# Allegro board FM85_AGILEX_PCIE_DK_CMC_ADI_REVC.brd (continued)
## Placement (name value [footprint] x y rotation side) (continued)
C1119  47uF  [0603]  144.66 71.47 180 bottom
C1120  47uF  [0603]  149.36 42.62 0 top
C1121  10uF  [0402]  127.09 57.31 240 bottom
C1122  10uF  [0402]  127.89 58.69 240 bottom
C1123  DNI  [0402]  127.81 55 240 bottom
C1124  47uF  [0603]  144.53 67.6 180 bottom
C1125  47uF  [0603]  144.66 63.6 180 bottom
C1126  DNI  [0603]  149.52 63.73 0 bottom
C1127  10uF  [0402]  144.79 58.11 90 bottom
C1128  10uF  [0402]  131.08 55.93 240 bottom
C1129  10uF  [0402]  130.28 57.31 60 bottom
C1130  10uF  [0402]  131.05 54.11 240 bottom
C1131  10uF  [0402]  128.73 55.93 120 bottom
C1132  47uF  [0603]  101.75 55.58 120 bottom
C1133  47uF  [0805]  150.88 55.45 270 bottom
C1134  47uF  [0805]  150.88 52.91 270 bottom
C1135  1uF  [0201]  118.41 47.25 30 bottom
C1136  1uF  [0201]  116.81 47.25 30 bottom
C1137  1uF  [0201]  115.22 47.25 30 bottom
C1138  1uF  [0201]  130.67 82.7 270 bottom
C1139  1uF  [0201]  119.01 71.55 210 bottom
C1140  1uF  [0201]  117.42 71.52 210 bottom
C1141  1uF  [0201]  115.83 71.52 210 bottom
C1142  1uF  [0201]  114.23 71.52 210 bottom
C1143  1uF  [0201]  113.63 47.25 30 bottom
C1144  1uF  [0201]  125.39 56.8 210 bottom
C1145  1uF  [0201]  124.71 52.54 30 bottom
C1146  1uF  [0201]  125.39 66 210 bottom
C1147  1uF  [0201]  108.38 65.02 90 bottom
C1148  1uF  [0201]  108.35 60.2 270 bottom
C1149  1uF  [0201]  107.48 51.58 90 bottom
C1150  1uF  [0201]  107.86 54.04 210 bottom
C1151  1uF  [0201]  107.25 55.53 30 bottom
C1152  22uF  [0603]  82.56 60.63 90 top
C1153  22uF  [0603]  86.11 55.32 0 bottom
C1154  22uF  [0603]  87.56 52.02 180 bottom
C1155  22uF  [0603]  80.91 66.88 90 top
C1159  1uF  [0201]  109.64 70.14 330 bottom
C1160  1uF  [0201]  109.64 71.06 330 bottom
C1161  10uF  [0402]  83.45 44.39 270 top
C1162  1uF  [0201]  124.95 47.94 90 bottom
C1163  1uF  [0201]  124.57 49.43 150 bottom
C1164  10uF  [0402]  109.95 85.64 180 top
C1165  1uF  [0201]  111.29 50.35 30 bottom
C1166  1uF  [0201]  112.83 68.87 30 bottom
C1167  10uF  [0402]  192.66 76.61 180 bottom
C1168  1uF  [0201]  125.64 54.71 150 bottom
C1169  1uF  [0201]  125.44 60.64 210 bottom
C1170  1uF  [0201]  125.55 62.03 150 bottom
C1171  1uF  [0201]  108.05 63.35 30 bottom
C1172  1uF  [0201]  108.66 61.86 210 bottom
C1173  1uF  [0201]  125.58 58.62 210 bottom
C1174  1uF  [0201]  107.25 57.37 30 bottom
C1175  1uF  [0201]  125.59 63.93 150 bottom
C1176  22uF  [0603]  94.9 37.17 270 bottom
C1177  22uF  [0603]  96.67 37.17 270 bottom
C1178  22uF  [0603]  109.19 36.44 0 bottom
C1179  22uF  [0603]  105.99 36.44 180 bottom
C1180  47uF  [0603]  83.39 54.84 180 top
C1181  47uF  [0603]  83.34 45.84 180 top
C1182  47uF  [0603]  83.39 64.54 180 top
C1183  47uF  [0603]  83.39 62.94 180 top
C1184  47uF  [0603]  83.34 43.05 180 top
C1185  47uF  [0603]  83.34 47.44 180 top
C1186  4.7uF  [0402]  111.16 70.19 60 bottom
C1187  4.7uF  [0402]  112.75 69.75 120 bottom
C1188  4.7uF  [0402]  112.75 70.67 120 bottom
C1189  1uF  [0201]  111.54 71.35 270 bottom
C1190  10uF  [0402]  114.72 85.64 180 top
C1191  4.7uF  [0402]  114.34 69.75 120 bottom
C1192  4.7uF  [0402]  116.71 69.67 240 bottom
C1193  4.7uF  [0402]  115.94 70.67 120 bottom
C1194  1uF  [0201]  114.43 70.71 30 bottom
C1195  10uF  [0402]  117.91 85.64 180 top
C1196  4.7uF  [0402]  118.33 70.23 300 bottom
C1197  4.7uF  [0402]  119.92 69.73 240 bottom
C1198  4.7uF  [0402]  119.92 70.65 240 bottom
C1199  1uF  [0201]  117.61 70.71 30 bottom
C1200  10uF  [0402]  121.11 85.64 180 top
C1201  4.7uF  [0402]  123.11 69.88 240 bottom
C1202  4.7uF  [0402]  123.21 70.75 240 bottom
C1203  4.7uF  [0402]  121.49 69.75 240 bottom
C1204  1uF  [0201]  121.5 70.61 150 bottom
C1205  10uF  [0402]  108.61 85.6 180 top
C1208  4.7uF  [0402]  109.56 47.66 120 bottom
C1209  4.7uF  [0402]  111.15 49.03 60 bottom
C1210  4.7uF  [0402]  111.15 48.11 60 bottom
C1211  1uF  [0201]  109.64 48.63 30 bottom
C1212  10uF  [0402]  114.25 33.14 0 top
C1213  4.7uF  [0402]  115.11 48.11 300 bottom
C1214  4.7uF  [0402]  114.32 49.11 60 bottom
C1215  4.7uF  [0402]  113.52 48.11 300 bottom
C1216  1uF  [0201]  112.83 48.63 30 bottom
C1217  10uF  [0402]  112.34 33.14 0 top
C1218  4.7uF  [0402]  116.71 48.11 300 bottom
C1219  4.7uF  [0402]  118.3 49.03 300 bottom
C1220  4.7uF  [0402]  118.3 48.11 300 bottom
C1221  1uF  [0201]  116.62 48.98 210 bottom
C1222  10uF  [0402]  120.57 33.14 0 top
C1223  4.7uF  [0402]  121.46 49 300 bottom
C1224  4.7uF  [0402]  121.1 47.37 180 bottom
C1225  4.7uF  [0402]  119.89 48.11 300 bottom
C1226  1uF  [0201]  119.81 48.98 210 bottom
C1227  10uF  [0402]  119.51 33.14 0 top
C1232  1uF  [0201]  113.93 68.13 270 bottom
C1233  1uF  [0201]  115.52 68.13 270 bottom
C1234  1uF  [0201]  117.12 68.13 270 bottom
C1235  1uF  [0201]  118.69 68.23 270 bottom
C1236  1uF  [0201]  115.52 50.65 90 bottom
C1237  1uF  [0201]  118.31 51.34 330 bottom
C1238  1uF  [0201]  117.17 50.52 90 bottom
C1239  10uF  [0402]  82.39 52.14 270 top
C1240  10uF  [0402]  82.39 70.14 270 top
C1241  10uF  [0402]  84.39 52.14 90 top
C1242  10uF  [0402]  84.39 70.14 270 top
C1243  10uF  [0402]  82.39 53.14 270 top
C1244  1uF  [0201]  123.8 48.17 150 bottom
C1245  1uF  [0201]  123.02 48.98 210 bottom
C1246  10uF  [0402]  103.96 55.47 120 bottom
C1247  10uF  [0402]  128.67 52.77 270 bottom
C1248  10uF  [0402]  128.74 54.05 300 bottom
C1249  10uF  [0402]  100.75 64.65 120 bottom
C1250  10uF  [0402]  100.77 62.83 120 bottom
C1251  10uF  [0402]  100.77 60.99 120 bottom
C1255  1uF  [0201]  113.07 85.65 270.3 top
C1256  1uF  [0201]  112.38 85.65 270 top
C1257  1uF  [0201]  107.06 70.71 150 bottom
C1258  1uF  [0201]  107.06 69.79 150 bottom
C1259  1uF  [0201]  107.06 68.87 150 bottom
C1260  1uF  [0201]  123.8 47.25 150 bottom
C1261  1uF  [0201]  122.39 48.06 330 bottom
C1262  1uF  [0201]  106.46 68.3 330 bottom
C1265  22uF  [0603]  149.36 48.34 180 top
C1266  DNI  [0805]  150.88 50.5 270 bottom
C1267  1uF  [0201]  106.38 50.85 150 bottom
C1268  1uF  [0201]  104.86 54.15 30 bottom
C1269  1uF  [0201]  108.66 69.22 210 bottom
C1270  1uF  [0201]  108.66 68.3 210 bottom
C1271  4.7uF  [0402]  105.55 56.39 300 bottom
C1272  1uF  [0201]  102.88 65.48 90 bottom
C1273  1uF  [0201]  101.47 65.67 330 bottom
C1277  DNI  [1206]  148.34 69.67 0 bottom
C1279  1uF  [0201]  130.25 53.64 150 bottom
C1280  1uF  [0201]  103.56 56.69 270 bottom
C1283  1uF  [0201]  108.05 71.06 330 bottom
C1284  4.7uF  [0402]  80.94 72.79 270 top
C1286  1000pF  [0402]  244.1 48.34 90 bottom
C1293  1uF  [0402]  57.41 37.04 0 bottom
C1294  1uF  [0402]  58.43 42.24 180 bottom
C1309  10uF  [C0805]  67.83 43 90 bottom
C1310  0.1uF  [0402]  68.71 44.66 270 bottom
C1311  10uF  [C0805]  71.89 43 270 bottom
C1312  0.1uF  [0402]  71 44.66 90 bottom
C1313  4.7uF  [0402]  73.54 47.58 270 bottom
C1314  10uF  [0402]  104.88 51.24 120 bottom
C1315  10uF  [0402]  125.47 55.93 120 bottom
C1316  DNI  [0402]  106.37 53.18 120 bottom
C1317  47uF  [0603]  144.94 59.6 180 bottom
C1318  47uF  [0603]  149.52 59.09 0 bottom
C1319  DNI  [0603]  147.74 67.6 0 bottom
C1320  47uF  [0603]  149.52 57.4 0 bottom
C1321  10uF  [0402]  101.56 52.79 75 bottom
C1322  10uF  [0402]  103.66 52.96 180 bottom
C1323  10uF  [0402]  103.98 54.56 300 bottom
C1324  10uF  [0402]  102.88 52.48 180 bottom
C1325  47uF  [0603]  83.34 49.14 180 top
C1326  47uF  [0603]  99.27 52.66 180 bottom
C1327  0.1uF  [0402]  53.47 105.87 180 top
C1328  22pF  [0603]  55.51 106 0 top
C1329  2.2nF  [0402]  58.81 105.87 0 top
C1330  47pF  [0402]  58.81 104.09 0 top
C1331  0.1uF  [0402]  48.9 103.58 270 top
C1332  10uF  [0402]  57.28 102.69 90 top
C1333  10uF  [0805]  58.94 99.77 180 top
C1334  4.7uF  [0603]  49.16 99.77 90 top
C1335  10uF  [0805]  47.25 99.77 180 top
C1336  4.7uF  [0603]  57.03 99.77 90 top
C1338  330uf  [1210]  58.3 95.33 270 top
C1339  330uf  [1210]  47.89 95.2 270 top
C1340  100uF  [0805]  57.54 94.69 0 bottom
C1341  100uF  [0805]  47.38 94.76 0 bottom
C1342  47uF  [0603]  54.36 94.69 90 bottom
C1343  47uF  [0603]  50.3 94.76 90 bottom
C1345  0.1uF  [0402]  205.85 51.95 270 bottom
C1346  2.2uF  [0402]  201 52.66 270 bottom
C1347  DNI  [0402]  203.33 49.25 270 bottom
C1348  DNI  [0402]  201.43 48.39 270 bottom
C1350  2.2uF  [0402]  198.43 53.6 180 top
C1351  100uF  [1206]  197.15 54.93 270 bottom
C1354  100uF  [1206]  193.48 55.05 0 bottom
C1355  DNI  [1206]  192.92 55.25 0 top
C1356  100pf  [0402]  200.96 50.14 270 bottom
C1360  22uF  [1206]  208.41 52.38 90 top
C1361  22uF  [1206]  208.41 49.86 270 bottom
C1364  1uF  [0402]  206.05 54 0 top
C1366  0.1uF  [0402]  207.14 43.41 180 bottom
C1367  2.2uF  [0402]  202.48 43.84 180 bottom
C1368  DNI  [0402]  205.24 40.67 270 bottom
C1369  DNI  [0402]  201.43 40.72 90 bottom
C1371  2.2uF  [0402]  199.4 45.67 180 top
C1372  100uF  [1206]  198.05 40.72 90 bottom
C1375  100uF  [1206]  198.05 45.54 270 bottom
C1376  DNI  [1206]  200.34 45.29 270 bottom
C1381  22uF  [1206]  209.32 42.09 270 bottom
C1382  22uF  [1206]  209.32 42.09 270 top
C1385  1uF  [0402]  208.26 45.47 0 top
C1386  100uF  [1206]  197.01 54.82 270 top
C1387  100uF  [1206]  197.62 46.43 270 top
C1388  100pf  [0402]  203.29 42.17 0 bottom
C1389  1uF  [0402]  59.95 37.04 0 bottom
C1390  1uF  [0402]  60.84 40.97 90 bottom
C1391  1uF  [0402]  60.84 39.45 90 bottom
C1392  1uF  [0402]  56.14 37.04 0 bottom
C1393  0.1uF  [0402]  57.92 32.97 180 top
C1394  0.1uF  [0402]  61.73 32.97 180 top
C1395  1uF  [0402]  204.86 62.18 90 bottom
C1396  1uF  [0402]  204.86 64.77 90 bottom
C1397  1uF  [0402]  214.46 59.69 270 bottom
C1398  1uF  [0402]  210.93 59.39 90 bottom
C1399  0.1uF  [0402]  216.92 57.1 90 bottom
C1400  0.1uF  [0402]  209.02 58.63 90 top
C1401  22uF  [0402]  109.53 55.91 300.6 bottom
C1402  22uF  [0402]  108.74 56.39 300 bottom
C1403  22uF  [0402]  123.1 62.95 120 bottom
C1404  22uF  [0402]  109.54 58.7 300 bottom
C1405  22uF  [0402]  107.97 58.71 120 bottom
C1406  22uF  [0402]  109.54 61.45 300 bottom
C1407  22uF  [0402]  109.15 64.43 0 bottom
C1408  22uF  [0402]  124.67 61.12 300 bottom
C1409  22uF  [0402]  123.15 53.49 300 bottom
C1410  22uF  [0402]  123.07 57.36 120 bottom
C1411  22uF  [0402]  118.36 49.98 300 bottom
C1412  22uF  [0402]  116.77 51.61 300 bottom
C1413  22uF  [0402]  110.24 52.85 300 bottom
C1414  22uF  [0402]  108.7 51.99 120 bottom
C1415  22uF  [0402]  113.62 51.65 120 bottom
C1416  22uF  [0402]  118.68 53.38 0 bottom
C1417  22uF  [0402]  120.25 53.38 180 bottom
C1418  22uF  [0402]  124.78 54.25 240 bottom
C1419  22uF  [0402]  124.7 57.81 240 bottom
C1420  22uF  [0402]  123.91 65.25 120 bottom
C1421  22uF  [0402]  124.79 63.36 240 bottom
C1422  22uF  [0402]  123.8 62.44 120 bottom
C1423  22uF  [0402]  123.85 67.07 300 bottom
C1424  22uF  [0402]  122.38 65.87 120 bottom
C1425  22uF  [0402]  121.45 68.85 240 bottom
C1426  22uF  [0402]  117.24 66.35 180 bottom
C1427  22uF  [0402]  113.57 65.59 124.4 bottom
C1428  22uF  [0402]  115.96 67.01 115.7 bottom
C1429  22uF  [0402]  112.73 66.04 121.8 bottom
C1430  22uF  [0402]  110.37 66.5 302.6 bottom
C1431  47uF  [0603]  115.32 63.83 270 bottom
C1432  330uF  [3528_2MM]  159.37 52.53 0 bottom
C1433  330uF  [3528_2MM]  159.37 79.23 0 bottom
C1435  330uF  [3528_2MM]  159.37 48.06 0 bottom
C1436  330uF  [3528_2MM]  159.37 75.72 0 bottom
C1437  330uF  [3528_2MM]  159.52 35.11 0 bottom
C1438  220uF  [1206]  130.72 87.68 90 bottom
C1439  47uF  [0603]  115.93 54.92 90 bottom
C1440  330uF  [3528_2MM]  105.42 86.08 180 bottom
C1441  330uF  [3528_2MM]  123.15 33.35 0 bottom
C1442  330uF  [3528_2MM]  96.15 85.93 180 bottom
C1443  220uF  [1206]  109.76 33.12 180 bottom
C1444  220uF  [1206]  116.85 33.58 180 bottom
C1445  47uF  [0603]  149.16 66.04 180 bottom
C1446  47uF  [0603]  125.14 85.4 0 bottom
C1447  1uF  [0201]  114.33 54.08 210 bottom
C1448  1uF  [0201]  119.51 53.77 270 bottom
C1449  1uF  [0201]  117.81 64.8 90 bottom
C1450  100u  [CAPC2012X110L50L]  144.05 89.13 270 bottom
C1451  0.1uF  [0402]  47.76 25.96 270 top
C1452  0.1uF  [0402]  47.76 26.98 270 top
C1456  2.2uF  [0402]  185.43 38.79 315 bottom
C1533  2.2uF  [0402]  183.09 59.34 270 bottom
C1557  470uF  [CAPMP7343X300L130X240N_P079IN]  160.97 85.78 0 bottom
C1558  100uF  [CAPC2012X110L50L]  159.39 89.16 90 bottom
C1559  100uF  [CAPC2012X110L50L]  159.42 82.04 90 bottom
C1560  22uF  [CAPC3216X135L50N]  170.93 77.08 0 bottom
C1561  22uF  [CAPC3216X135L50N]  171.03 88.22 0 bottom
C1562  22uF  [CAPC3216X135L50N]  170.51 83.8 0 bottom
C1563  22uF  [CAPC3216X135L50N]  170.51 81.44 0 bottom
C1564  1uF  [CAPC1005X60L20L]  170.19 78.97 90 bottom
C1565  1uF  [CAPC1005X60L20L]  171.13 89 270 top
C1575  470uF  [CAPMP7343X300L130X240N_P079IN]  161.08 69.68 0 bottom
C1576  100uF  [CAPC2012X110L50L]  159.41 66.28 90 bottom
C1577  100uF  [CAPC2012X110L50L]  159.43 73.15 90 bottom
C1578  22uF  [CAPC3216X135L50N]  170.34 66.94 0 bottom
C1579  22uF  [CAPC3216X135L50N]  170.94 63.47 0 bottom
C1580  22uF  [CAPC3216X135L50N]  170.39 71.51 0 bottom
C1581  22uF  [CAPC3216X135L50N]  170.4 74.02 0 bottom
C1582  1uF  [CAPC1005X60L20L]  170.75 65.11 90 bottom
C1622  470uF  [CAPMP7343X300L130X240N_P079IN]  160.93 77.11 0 top
C1623  470uF  [CAPMP7343X300L130X240N_P079IN]  161.63 63.2 0 top
C1624  470uF  [CAPMP7343X300L130X240N_P079IN]  161.96 90.53 0 top
C1625  330 uF  [CT7343-43]  170.4 77.17 180 top
C1626  330 uF  [CT7343-43]  170.52 63.15 180 top
C1627  330 uF  [CT7343-43]  170.5 48.74 180 top
C1628  330 uF  [CT7361-20]  187.64 54.66 270 bottom
C1629  330 uF  [CT7343-43]  169.7 33.3 180 top
C1630  22uF  [CAPC3216X135L50N]  185.81 61.6 270 top
C1631  22uF  [CAPC3216X135L50N]  185.43 61.6 270 bottom
C1632  22uF  [CAPC3216X135L50N]  187.61 61.62 270 bottom
C1633  22uF  [CAPC3216X135L50N]  187.99 61.62 270 top
C1714  4.7uF  [0402]  186.11 58.47 90 top
C1715  2.2uF  [0603]  186.14 54.92 0 top
C1716  2.2uF  [0603]  186.14 57.33 0 top
C1718  1uF  [0402]  181.34 63.81 0 bottom
C1719  330pF  [0603]  178.65 62.16 90 bottom
C1720  100pF  [0402]  176.26 60.62 270 top
C1721  2200pF  [0402]  176.62 59.82 270 top
C1728  10uF  [0402]  173.51 69.01 0 bottom
C1729  1uF  [0402]  173.55 70.72 180 bottom
C1730  1uF  [0402]  170.82 61.81 90 bottom
C1731  1uF  [0402]  170.6 50.15 90 bottom
C1732  22uF  [CAPC3216X135L50N]  170.42 51.87 0 bottom
C1733  22uF  [CAPC3216X135L50N]  170.47 48.46 0 bottom
C1734  22uF  [CAPC3216X135L50N]  170.47 56.75 0 bottom
C1735  22uF  [CAPC3216X135L50N]  170.48 59.19 0 bottom
C1738  470uF  [CAPMP7343X300L130X240N_P079IN]  161.01 58.86 0 bottom
C1739  100uF  [CAPC2012X110L50L]  159.43 55.41 90 bottom
C1740  100uF  [CAPC2012X110L50L]  159.43 62.24 90 bottom
C1741  1uF  [0402]  170.6 46.73 90 bottom
C1742  1uF  [0402]  171.41 36.22 270 top
C1743  22uF  [CAPC3216X135L50N]  170.45 36.89 0 bottom
C1744  22uF  [CAPC3216X135L50N]  170.45 39.25 0 bottom
C1745  22uF  [CAPC3216X135L50N]  170.37 41.87 0 bottom
C1746  22uF  [CAPC3216X135L50N]  170.38 44.31 0 bottom
C1749  470uF  [CAPMP7343X300L130X240N_P079IN]  160.93 42.02 0 bottom
C1750  100uF  [CAPC2012X110L50L]  159.44 38.53 90 bottom
C1751  100uF  [CAPC2012X110L50L]  159.44 31.98 90 bottom
C1886  470uF  [D2E]  58.3 69.93 180 bottom
C1887  100uF  [1206]  73.35 63.74 90 bottom
C1888  100uF  [1206]  68.21 63.83 90 bottom
C1889  100uF  [1206]  75.77 63.74 90 bottom
C1890  220 uF  [CT7361-20]  64.6 81.4 90 bottom
C1891  22uF  [1206]  78.31 74.56 90 bottom
C1892  22uF  [1206]  75.8 74.56 90 bottom
C1893  22uF  [1206]  63.25 74.47 90 bottom
C1894  22uF  [1206]  65.71 74.47 90 bottom
C1958  22uF  [1206]  182.4 18.87 90 bottom
C1959  22uF  [1206]  193.07 18.93 90 bottom
C1960  1uF  [0402]  185.77 20.7 90 bottom
C1961  2.2uF  [0603]  180.32 15.83 270 bottom
C1962  100uF  [1206]  184.67 15.5 0 bottom
C1963  100uF  [1206]  190.89 15.5 180 bottom
C1964  100uF  [1206]  193.81 14.68 180 top
C1966  0.1uF,DNI  [0402]  184.27 24.61 180 bottom
C1967  0.1uF  [0402]  181.13 23 0 bottom
C2004  1.5nF  [0402]  191.24 78.06 180 bottom
C2028  47pF  [0402]  174.51 52.78 0 top
C7192  100nF  [C0402]  10.78 20.25 90 top
C7394  4u7  [C0402]  12.86 15.29 90 top
C7395  100nF  [C0402]  12.86 16.13 90 top
C7396  100nF  [C0402]  15.35 19.76 0 top
C7397  0.1uF  [0402]  4.91 23.35 315 bottom
C7398  0.1uF  [0402]  7.03 22.92 315 bottom
C7399  0.1uF  [0402]  135.59 36.02 270 top
C7400  0.1uF  [0402]  129.71 35.94 90 top
C7401  0.1uF  [0402]  47.2 20.78 0 top
C7402  0.1uF  [0402]  40.48 19.87 0 top
C7403  0.1uF  [0402]  201.07 20.48 180 top
C7404  0.1uF  [0402]  228.2 105.97 0 bottom
C7405  10uF  [0603]  26.42 31.91 90 bottom
C7406  1uF  [0402]  26.47 28.43 180 bottom
C7422  2.2uF  [0402]  186.47 94.39 180 bottom
C7423  22uF  [0603]  191.77 91.32 270 top
C7424  22uF  [0603]  193.21 91.32 270 top
C7425  22uF  [0603]  194.64 91.32 270 top
C7426  22uF  [0603]  196.08 91.32 270 top
C7427  22uF  [0603]  197.51 91.32 270 top
C7428  22uF  [0603]  199.74 92.34 0 top
C7429  22uF  [0603]  192.74 94.69 90 bottom
C7430  22uF  [0603]  191.37 95 90 bottom
C7431  22uF  [0603]  188.9 91.32 270 top
C7432  22uF  [0603]  190.34 91.32 270 top
C7433  0.1uF  [0402]  187.14 88.5 270 bottom
C7434  0.01uF  [0402]  189.29 94.52 90 bottom
C7435  0.1uF  [0402]  118.97 85.66 180 top
C7436  0.1uF  [0402]  119.98 85.66 180 top
C7437  0.1uF  [0402]  122.22 71.62 315 bottom
C7438  0.1uF  [0402]  120.69 71.65 302.9 bottom
C7439  0.01uF  [0402]  204.49 18.92 90 bottom
C7442  47uF  [C1206]  66.68 40.87 0 bottom
C7461  1500pF  [0402]  181.95 42.8 180 bottom
C7462  150pF  [0402]  183.03 41.72 180 bottom
C7463  0.1uF,DNI  [0402]  179.41 47.37 270 bottom
C7464  0.1uF,DNI  [0402]  195.08 44.64 0 top
C7465  150uF  [7343P_H2MM]  190.3 51.77 180 top
C7466  22uF  [1206]  189.57 37.39 90 bottom
C7467  22uF  [1206]  191.78 44.07 270 bottom
C7468  22uF  [1206]  189.69 44.02 270 bottom
C7469  22uF  [1206]  187.38 37.26 90 bottom
C7470  22uF  [1206]  186.39 40.69 0 bottom
C7471  10uF  [1206]  191.83 37.42 90 bottom
C7472  100uF  [1206]  181.87 30.53 90 bottom
C7473  100uF  [1206]  184.47 51.82 270 top
C7474  100uF  [1206]  182.19 51.82 270 top
C7475  100uF,DNI  [1206]  179.55 30.53 90 bottom
C7477  470uF  [2917]  180.36 29.09 180 top
C7478  470uF  [2917]  190.16 29.09 0 top
C7479  100uF  [1206]  186.44 30.53 90 bottom
C7480  100uF  [1206]  179.9 51.82 270 top
C7481  100uF  [1206]  184.15 30.53 90 bottom
C7517  22uF  [1206]  73.59 91.47 180 bottom
C7518  0.01uF  [0402]  68.04 86.55 270 bottom
C7519  47uF  [C1206]  74.23 82.81 180 bottom
C7520  47uF  [C1206]  78.72 90.6 180 top
C7521  22uF  [1206]  25.86 53.32 90 bottom
C7522  0.01uF  [0402]  16.87 58.77 270 bottom
C7523  47uF  [C1206]  27.16 61.26 270 bottom
C7524  47uF  [C1206]  25.47 66.83 270 bottom
C7525  1uF  [0402]  196.27 81.41 180 bottom
C7526  1uF  [0402]  71.53 89.31 90 bottom
C7556  1uF  [CAPC1005X60L20L]  170.1 75.53 90 bottom
C7557  470uF  [CAPMP7343X300L130X240N_P079IN]  161.37 48.69 0 top
C7558  4.7uF  [0402]  187.15 66.3 180 top
C7559  4.7uF  [0402]  187.15 69.45 0 top
C7560  10nF  [0402]  191.88 68.28 90 bottom
C7561  4.7uF  [0402]  193.88 67.19 0 top
C7562  4.7uF  [0402]  193.89 69.93 0 top
C7563  10nF  [0402]  200.59 67.87 0 top
C7564  22uF  [1206]  184.27 69.29 180 bottom
C7565  22uF  [1206]  180.47 68.1 90 bottom
C7566  100pf  [0402]  178.25 68.96 270 top
C7567  22nF  [0402]  184.92 67.36 0 top
C7568  1nF  [0402]  182.3 66 90 top
C7569  3.3nF  [0402]  184.92 66.45 0 bottom
C7571  47uF  [C1206]  74.99 32.82 180 bottom
C7572  22uF  [CAPC3216X135L50N]  191.41 63.74 0 bottom
C7574  1uF  [0402]  71.94 75.69 180 bottom
C7575  0.1uF  [0402]  41.85 20.08 180 top
C7578  1uF  [0402]  173.41 84.71 180 bottom
C7579  10uF  [0402]  173.51 82.78 0 bottom
C7580  1uF  [0402]  174.52 56.89 0 top
C7581  10uF  [0402]  174.52 55.02 180 top
C7582  1uF  [0402]  175.27 42.67 0 top
C7583  10uF  [0402]  174.95 40.59 180 top
C7584  470uF  [D2E]  58.28 65.13 180 bottom
C7585  100uF  [1206]  78.31 63.74 90 bottom
C7586  100uF  [1206]  65.58 63.74 90 bottom
C7587  100uF  [1206]  80.71 63.74 90 bottom
C7588  220 uF  [CT7361-20]  204.83 88.34 0 top
C7589  22uF  [1206]  198.61 78.18 90 top
C7590  22uF  [1206]  198.25 85.3 270 bottom
C7591  22uF  [1206]  198.61 83.9 270 top
C7592  22uF  [1206]  197.83 76.07 90 bottom
C7593  100uF  [1206]  176.97 77.08 0 top
C7594  100uF  [1206]  181.18 75.28 90 bottom
C7595  100uF  [1206]  181.19 75.33 90 top
C7596  470uF  [D2E]  177.58 75.46 270 bottom
C7597  100uF  [1206]  181.43 85.19 90 bottom
C7598  100uF  [1206]  181.32 85.16 90 top
C7599  100uF  [1206]  179.13 85.19 90 top
C7600  470uF  [D2E]  177.58 85.11 270 bottom
C7602  1uF  [0402]  196.45 66.8 180 bottom
C7603  22uF  [CAPC3216X135L50N]  192.34 60.25 0 top
C7604  1uF  [0402]  70.83 35.07 270 bottom
C7605  22uF  [1206]  72.8 40.76 180 bottom
C7606  22uF  [1206]  220.67 98.38 90 top
C7607  22uF  [1206]  205.26 98.38 90 top
C7608  1uF  [0402]  211.04 99.98 270 top
C7609  2.2uF  [0603]  206.5 105.2 90 top
C7610  100uF  [1206]  209.7 105.63 270 top
C7611  100uF  [1206]  217.32 105.71 270 top
C7612  100uF  [1206]  213.51 105.66 270 top
C7614  0.1uF,DNI  [0402]  212.32 97.35 180 top
C7615  0.1uF  [0402]  214.36 98.68 0 top
C7616  22uF  [1206]  77.2 54.77 90 bottom
C7617  22uF  [1206]  65.65 54.54 90 bottom
C7618  1uF  [0402]  69.48 55.04 180 bottom
C7619  2.2uF  [0603]  72.02 55.15 90 bottom
C7620  100uF  [1206]  72.22 49.94 0 top
C7621  100uF  [1206]  77.17 50.21 180 top
C7622  100uF  [1206]  67.24 49.94 180 top
C7624  0.1uF,DNI  [0402]  67.55 60.33 180 bottom
C7625  0.1uF  [0402]  64.38 58.67 0 bottom
C7626  22uF  [1206]  26.09 41.25 0 bottom
C7627  0.01uF  [0402]  32.87 36.92 0 bottom
C7630  22uF  [1206]  15.65 43.31 270 bottom
C7631  0.01uF  [0402]  21.55 36.53 0 bottom
C7632  47uF  [C1206]  21.12 41.05 0 bottom
C7634  47uF  [C1206]  32.96 43.41 0 bottom
C7636  22uF  [1206]  5.72 37.54 90 bottom
C7637  0.01uF  [0402]  9.71 37.19 0 bottom
C7638  47uF  [C1206]  9.87 43.16 0 bottom
C7639  47uF  [C1206]  9.87 40.88 0 bottom
C7640  22uF  [1206]  15.42 37.14 90 bottom
C7641  47uF  [C1206]  21.12 43.34 0 bottom
C7642  22pF  [0603]  24.01 37.54 0 bottom
C7643  22pF  [0603]  35.16 36.91 0 bottom
C7644  22pF  [0603]  16.39 62.41 90 bottom
C7645  22pF  [0603]  12.71 37.16 0 bottom
C7646  22uF  [1206]  26.07 43.56 0 bottom
C7647  47uF  [C1206]  32.96 41.15 0 bottom
C7648  22uF  [1206]  4 44.79 0 bottom
C7649  22uF  [1206]  28 53.32 90 bottom
C7650  1uF  [0402]  207.86 19.46 180 bottom
C7651  22pF  [0603]  68.56 83.47 270 bottom
C7652  22pF  [0603]  202.43 15.98 270 bottom
C7653  47uF  [C1206]  210.33 14.86 180 bottom
C7654  0.1uF  [0402]  192.06 61.6 270 bottom
C7655  1uF  [0402]  196.78 84.43 0 top
C7656  1uF  [0402]  68.13 75.7 90 bottom
C7660  1.5nF  [0402]  75.11 71.28 270 bottom
C7661  1000pF,DNI  [1206]  77.12 69.75 90 bottom
C7663  360pF,DNI  [0402]  188.22 78.21 270 bottom
C7664  0.1uF  [CAPC1005X60L20L]  178.7 58.12 0 bottom
C7665  0.01uF  [0402]  197.72 64.62 180 top
C7666  47uF  [C1206]  210.38 17 180 bottom
C7667  22uF  [1206]  209.18 25.78 270 bottom
C7668  22uF  [1206]  207.02 25.78 270 bottom
C7669  0.47uF  [0402]  176.21 63.27 90 bottom
C7670  0.47uF  [0402]  182.58 63.81 0 bottom
C7671  0.47uF  [0402]  175.62 62.77 180 top
C7672  0.47uF  [0402]  180.4 63.81 0 bottom
C7674  22uF  [1206]  68.76 91.49 0 bottom
C7676  12pF  [0402]  8.8 19.94 0 top
C7678  0.1uF  [CAPC1005X60L20L]  178.7 59.9 0 bottom
C7679  100uF  [CAPC2012X110L50L]  151.22 90.38 0 top
C7680  100uF  [CAPC2012X110L50L]  153.57 90.38 0 top
C7681  47pF  [0402]  173.54 74.12 0 bottom
C7682  47pF  [0402]  174.48 88.12 180 top
C7683  100pF,DNI  [0402]  198.99 64.62 180 top
C7684  22uF  [CAPC3216X135L50N]  191.42 60.11 0 bottom
C7685  22uF  [CAPC3216X135L50N]  198.53 68.35 270 bottom
C7686  47pF  [0402]  173.49 80.98 180 bottom
C7687  100uF  [CAPC2012X110L50L]  159.4 64.26 90 bottom
C7688  100uF  [CAPC2012X110L50L]  151.06 61.17 270 bottom
C7689  47pF  [0402]  174.5 66.37 180 top
C7690  47pF  [0402]  174.51 37.54 180 top
C7691  47pF  [0402]  175.52 44.86 90 top
C7692  47pF  [0402]  174.88 59.82 90 top
C7693  100uF  [CAPC2012X110L50L]  159.35 45.4 90 bottom
C7694  100uF  [CAPC2012X110L50L]  154.19 48.29 270 bottom
C7695  100uF  [CAPC2012X110L50L]  156.01 31.14 0 bottom
C7696  100uF  [CAPC2012X110L50L]  151.14 44.71 270 bottom
C7697  1uF  [0402]  18.35 44.2 180 bottom
C7698  100pF,DNI  [0402]  22.99 39.07 0 bottom
C7699  47uF  [C1206]  21.04 45.85 0 bottom
C7700  1uF  [0402]  30.21 44.3 180 bottom
C7701  47uF  [C1206]  37.8 44.63 180 bottom
C7702  100pF,DNI  [0402]  35.03 39.27 0 bottom
C7703  1uF  [0402]  7.12 43.23 180 bottom
C7704  1uF  [0402]  27.24 58.14 90 bottom
C7706  100pF,DNI  [0402]  11.69 38.81 0 bottom
C7707  100pF,DNI  [0402]  21.61 64.09 270 bottom
C7708  47uF  [C1206]  23.3 66.8 270 bottom
C7709  47uF  [C1206]  13.34 43.26 270 bottom
C7711  100pF,DNI  [0402]  71 83.52 270 bottom
C7712  47uF  [C1206]  78.72 88.42 180 top
C7713  22uF  [1206]  69.63 33.02 0 bottom
C7714  1uF  [0402]  73.95 88.14 270 bottom
C7715  100pf  [0402]  179.18 15.6 180 bottom
C7716  100pf  [0402]  206.62 95.29 180 top
C7717  100pf  [0402]  63.28 54.84 0 bottom
C7718  3.3nF, DNI  [0402]  183.65 66.75 270 bottom
C7719  22uF  [1206]  179.22 71.56 0 top
C7720  10pF  [0402]  65.03 60.53 0 bottom
C7721  10pF  [0402]  190.02 26.24 0 bottom
C7722  10pF  [0402]  211.52 96.32 0 top
C7723  100pf  [0402]  67.93 38.74 0 bottom
C7725  100pF,DNI  [0402]  205.06 16.26 270 bottom
C7726  2.2nF  [0402]  169.27 15.22 270 top
C7727  2.2nF  [0402]  171.48 27.64 0 top
C7728  2.2nF  [0402]  161.88 24.29 180 top
C7729  2.2nF  [0402]  162.03 17.27 0 top
C7730  2.2nF  [0402]  161.88 26.8 180 top
C7731  2.2nF  [0402]  161.96 21.31 180 top
C7732  2.2nF  [0402]  171.41 21.31 180 top
C7733  2.2nF  [0402]  171.41 23.6 0 top
C7734  2.2nF  [0402]  167.82 24.06 90 bottom
C7735  3.3nF  [0402]  169.5 26.44 90 bottom
C7736  3.3nF  [0402]  163.56 24.46 0 bottom
C7737  4.7nF  [0402]  170.42 28.93 270 bottom
C7738  4.7nF  [0402]  170.42 28.1 270 bottom
C7739  4.7nF  [0402]  163.02 28.93 90 bottom
C7740  0.47uF  [0402]  165.62 28.1 270 bottom
C7741  0.47uF  [0402]  169.96 21.39 0 bottom
C7742  0.47uF  [0402]  169.5 24.05 90 bottom
C7743  2.2nF  [0402]  67.37 24.36 180 top
C7744  2.2nF  [0402]  67.44 21.38 180 top
C7745  2.2nF  [0402]  67.52 17.35 0 top
C7746  2.2nF  [0402]  73.03 24.89 0 bottom
C7747  2.2nF  [0402]  76.89 17.2 180 top
C7748  2.2nF  [0402]  67.32 27.64 180 top
C7749  2.2nF  [0402]  76.97 27.71 0 top
C7750  2.2nF  [0402]  76.89 23.67 0 top
C7751  2.2nF  [0402]  76.89 21.38 180 top
C7752  3.3nF  [0402]  74.99 26.51 90 bottom
C7753  3.3nF  [0402]  69.04 24.53 0 bottom
C7754  4.7nF  [0402]  68.51 29 90 bottom
C7755  4.7nF  [0402]  75.9 29 270 bottom
C7756  4.7nF  [0402]  75.9 28.17 270 bottom
C7757  0.47uF  [0402]  68.18 23.22 0 bottom
C7758  0.47uF  [0402]  71.51 28.68 0 bottom
C7759  0.47uF  [0402]  74.99 24.12 90 bottom
C7760  4.7uF  [0402]  68.46 36.25 270 bottom
C7761  0.1uF  [0402]  233.13 38.61 0 top
C7764  47pF  [0402]  229.72 37.82 270 top
C7765  0.1uF  [0402]  236.15 42.37 90 bottom
C7766  10uF  [0805]  230.31 41.53 180 bottom
C7767  10uF  [0805]  238.94 44.61 0 top
C7768  4.7uF  [0603]  237.04 44.4 270 top
C7769  10uF  [0805]  228.1 44.2 0 top
C7770  4.7uF  [0603]  229.88 44.17 270 top
C7771  330uF  [7343P]  239.61 54.92 0 top
C7772  330uF  [7343P]  228.15 54.92 180 top
C7773  100uF  [0805]  228.3 51.44 270 top
C7774  100uF  [0805]  238.46 51.59 90 top
C7775  47uF  [0603]  238.16 49.76 0 top
C7776  47uF  [0603]  228.49 49.61 180 top
C7777  1uF  [0402]  205.26 22.94 90 bottom
C7778  1uF  [0402]  27.19 56.34 90 bottom
C7779  1uF  [0402]  5.42 40.8 0 bottom
C7780  100pf  [0402]  231.52 37.47 90 top
C7781  10pF  [0402]  232.06 38.64 0 top
C7783  220 uF  [CT7361-20]  240.7 38.61 270 bottom
CN1  0.1uF  [CAP_PACK_4_1206]  64.75 15.97 270 bottom
CN2  0.1uF  [CAP_PACK_4_1206]  69.68 13.31 0 bottom
CN3  0.1uF  [CAP_PACK_4_1206]  64.75 20.32 270 bottom
CN4  0.1uF  [CAP_PACK_4_1206]  175.14 15.98 270 top
CN5  0.1uF  [CAP_PACK_4_1206]  175.14 23.87 270 top
CN6  0.1uF  [CAP_PACK_4_1206]  175.14 19.89 270 top
D1  GREEN_LED  [LED_0603]  2.45 68.65 270 top
D2  APHB1608CGKSYKC  [LED0603_4PIN_APHB1608]  6.45 68.65 270 top
D3  GREEN_LED  [LED_0603]  10.45 68.65 270 top
D4  APHB1608CGKSYKC  [LED0603_4PIN_APHB1608]  14.45 68.65 270 top
D5  GREEN_LED  [LED_0603]  250.83 41.23 0 top
D6  BLUE LED  [LED_0603]  250.83 45.8 0 top
D7  GREEN_LED  [LED_0603]  250.83 39.7 0 top
D8  GREEN_LED  [LED_0603]  250.83 38.18 0 top
D9  RED_LED  [LED_0603]  250.83 44.27 0 top
D10  GREEN_LED  [LED_0603]  250.83 36.65 0 top
D11  GREEN_LED  [LED_0603]  250.83 42.75 0 top
D12  5p0SMDJ12A  [TVS_5P0SMDJ12A]  225.68 92.76 0 bottom
D13  5p0SMDJ12A  [TVS_5P0SMDJ12A]  205.54 70.28 0 bottom
D14  GREEN_LED  [LED_0603]  15.07 107.21 180 top
D17  PMEG2005AEL,315  [DIO_SOD882]  183.65 81.44 90 bottom
D18  PMEG2005AEL,315  [DIO_SOD882]  64.95 67.26 0 bottom
EU1  MAX31730ATC+  [LCC12_S30_50DF25X17MA]  73.12 80.24 270 top
EU2  MAX31730ATC+  [LCC12_S30_50DF25X17MA]  170.47 91.39 90 bottom
FB1  220ohm  [0402]  148.72 47.58 180 bottom
FB5  220ohm  [0402]  51.46 20.85 90 bottom
FB6  220ohm  [0402]  59.44 22.71 270 bottom
FB7  220ohm  [0402]  56.78 18.37 0 bottom
FB8  80ohm  [0805]  60.14 29.23 270 bottom
FB9  220ohm  [0402]  42.17 43.13 90 bottom
FB10  220ohm  [0402]  56.01 43.51 90 bottom
FB13  220ohm  [0402]  212.73 68.02 270 bottom
FB16  600 Ohm, 0.5A, 0.35DCR  [0603]  8.77 26.34 180 bottom
FB26  0.1uH, 19A  [SL1616A-R10MHF]  139.41 86.63 0 top
FB29  220ohm  [0402]  80.5 69.78 0 bottom
FB30  22ohm@100Mhz 8A  [0603]  84.46 59.26 180 bottom
FB31  22ohm@100Mhz 8A  [0603]  85.16 70.94 270 bottom
FB32  22ohm@100Mhz 8A  [0603]  84.97 45.29 180 bottom
FB33  22ohm@100Mhz 8A  [0603]  84.46 61.29 180 bottom
FB40  220ohm  [0402]  64.98 43 270 bottom
FB41  22ohm@100Mhz 8A  [0603]  84.46 57.36 180 bottom
HW1  -  [LIGHTPIPE_P-U90-1101-T00A-BP]  12.45 69.7 270 top
J1  DDR4x72x288  [DDR4DIMM_SMT]  132.47 96.34 180 top
J2  DDR4x72x288  [DDR4DIMM_SMT]  132.47 103.96 180 top
J3  -  [2027180100]  46.1 81.04 0 top
J4  -  [2027180100]  46.1 56.25 0 top
J5  PCIE_Slot  [PCIX-16PORT]  45.65 4.1 0 top
J6  MCIO_74P_G97V22312HR  [SCONN74_K64129002_PIP]  220.71 16.58 180 top
J7  MCIO_74P_G97V22312HR  [SCONN74_K64129002_PIP]  220.71 45.29 180 top
J8  MICRO_USB_CONN  [MOLEX-MICRO-USB-47589-001]  1.45 28.3 90 top
J9  FAN_Conn  [MOLEX_0470533000]  248.17 24.46 270 top
J10  70247-1051  [MOLEX_70247-1051]  224.16 99.4 0 top
J11  PCIe 2x4 ATX  [MLX_SD-5569_8POS_RA]  240.11 96.54 270 top
J12  TSW-103-08-G-S  [1X3_HDR_TH]  227.05 17.4 0 top
J13  TSW-103-08-G-S  [1X3_HDR_TH]  237.03 17.47 0 top
J14  TSW-103-08-G-S  [1X3_HDR_TH]  2.42 37.67 90 top
J15  TSW-103-08-G-S  [1X3_HDR_TH]  235.88 25.29 90 top
L1  1uH  [IFSC1008ABER1R0M01]  46.77 78.85 0 bottom
L2  1uH  [IFSC1008ABER1R0M01]  46.77 84.94 0 bottom
L3  1uH  [IFSC1008ABER1R0M01]  46.77 87.99 0 bottom
L4  1uH  [IFSC1008ABER1R0M01]  46.77 54.05 0 bottom
L5  1uH  [IFSC1008ABER1R0M01]  46.77 60.15 0 bottom
L6  1uH  [IFSC1008ABER1R0M01]  46.77 63.2 0 bottom
L11  BLM15AG221SN1  [0402]  21.37 35.08 270 bottom
L12  BLM15AG221SN1  [0402]  23.51 33.73 270 bottom
L13  BLM15AG221SN1  [0402]  20.97 32.17 180 bottom
L14  BLM15AG221SN1  [0402]  29.55 27.41 0 bottom
L20  0.82uH  [XEL4020-821]  39.02 95.15 270 top
L21  0.82uH  [XEL4020-821]  198.91 35.26 180 top
L22  0.20uH  [XEL4030-201ME]  53.09 95.2 270 top
L23  72 nH  [IND_FP0805-CUS]  162.23 56.06 180 top
L26  1uH  [IFSC1008ABER1R0M01]  180.6 68.4 90 top
L27  72 nH  [IND_FP0805-CUS]  162.23 83.87 180 top
L28  72 nH  [IND_FP0805-CUS]  162.23 70.16 180 top
L29  72 nH  [IND_FP0805-CUS]  162.23 41.35 180 top
L30  0.35 uH  [IND_XGL5030]  233.36 49.35 90 top
MTH1  MT_HOLE_GND  [MH_D125C175T_TB315]  249.01 16.65 0 top
MTH2  MT_HOLE_GND  [MH_D125C175T_TB315]  7.5 104.65 180 bottom
MTH4  MT_HOLE_GND  [MH_D125C175T_TB315]  249.03 106.14 0 top
MTH5  MT_HOLE_GND  [MH_D125C175T_TB315]  7.5 9.35 0 top
NOREF  -  []  74.4 33.94 90 top
NOREF#2  -  []  233.36 47.7 90 top
NOREF#3  -  []  178.59 64.54 0 top
NOREF#4  -  []  68.88 38.66 90 top
NOREF#5  -  []  45 0.5 0 top
NOREF#6  -  []  173.6 66.16 90 top
NOREF#7  -  []  197.99 58.31 90 top
NOREF#8  -  []  237.65 34.96 0 top
NOREF#9  -  []  205.36 96.07 0 top
NOREF#10  -  [unnamed#2]  5.67 96.01 0 top
NOREF#11  -  []  200.26 59.06 90 top
NOREF#12  -  [unnamed#3]  117.46 13.51 0 top
NOREF#13  -  []  159.67 56.06 0 top
NOREF#14  -  []  173.66 72.64 90 top
NOREF#15  -  []  254 12.75 0 top
NOREF#16  -  []  61.55 83.85 0 top
NOREF#17  -  []  33.35 4.5 0 top
NOREF#18  -  [unnamed#3]  100.19 10.36 0 top
NOREF#19  -  []  129.3 0.5 0 top
NOREF#20  -  []  41.35 10.92 0 top
NOREF#21  -  [unnamed#3]  173.28 27.01 0 top
NOREF#22  -  []  7.75 113.69 0 top
NOREF#23  -  []  181.13 17.48 0 top
NOREF#24  -  []  168.58 87.2 90 top
NOREF#25  -  []  68.15 33.94 0 top
NOREF#26  -  []  166.04 58.92 0 top
NOREF#27  -  [unnamed#3]  84.43 10.36 0 top
NOREF#28  -  []  41.35 10.92 0 top
NOREF#29  -  []  159.67 83.87 0 top
NOREF#30  -  []  7.5 94.75 0 top
NOREF#31  -  []  44.45 9.62 0 top
NOREF#32  -  []  168.6 74.16 0 top
NOREF#33  -  []  168.54 44.35 90 top
NOREF#34  -  []  7.5 104.88 0 top
NOREF#35  -  []  237.65 34.96 90 top
NOREF#36  -  []  166.04 72.64 0 top
NOREF#37  -  []  60.08 -68.63 0 top
NOREF#38  -  []  139.03 11 0 top
NOREF#39  -  []  166.04 30.12 0 top
NOREF#40  -  []  0 4.5 0 top
NOREF#41  -  []  36.14 14.57 0 top
NOREF#42  -  []  178.59 56.54 90 top
NOREF#43  -  []  147.3 10.21 0 top
NOREF#44  -  []  179.98 25.79 0 top
NOREF#45  -  []  58.1 0.5 0 top
NOREF#46  -  []  7.5 94.75 0 top
NOREF#47  -  []  7.5 9.35 0 top
NOREF#48  -  []  230.62 51.99 0 top
NOREF#49  -  [unnamed#3]  68.68 10.36 0 top
NOREF#50  -  []  0.01 123.85 0 top
NOREF#51  -  [unnamed#3]  244.47 21.49 0 top
NOREF#52  -  []  183.51 88.74 0 top
NOREF#53  -  []  38.32 14.29 90 top
NOREF#54  -  []  166.04 44.83 0 top
NOREF#55  -  []  173.66 30.12 90 top
NOREF#56  -  []  201.18 91.39 0 top
NOREF#57  -  []  74.4 33.94 90 top
NOREF#58  -  []  68.15 33.94 0 top
NOREF#59  -  []  68.85 77.75 90 top
NOREF#60  -  [unnamed#3]  242.37 101.24 0 top
NOREF#61  -  []  190.69 64.41 0 top
NOREF#62  -  []  0 111.15 0 top
NOREF#63  -  []  182.39 67.57 0 top
NOREF#64  -  []  35.82 16.29 0 top
NOREF#65  -  []  62.67 64.68 90 top
NOREF#66  -  []  58.29 0.31 0 top
NOREF#67  -  []  173.52 52.16 90 top
NOREF#68  -  []  -309.9 -46.1 0 top
NOREF#69  -  []  168.48 88.2 0 top
NOREF#70  -  []  179.98 16.79 90 top
NOREF#71  -  [unnamed#2]  91.2 10.37 0 top
NOREF#72  -  []  63.23 52.46 90 top
NOREF#73  -  []  159.67 70.16 0 top
NOREF#74  -  []  182.64 67.32 0 top
NOREF#75  -  []  168.62 59.16 90 top
NOREF#76  -  []  168.52 60.16 0 top
NOREF#77  -  []  168.44 45.35 0 top
NOREF#78  -  []  0 4.5 0 top
NOREF#79  -  []  7.5 94.75 0 top
NOREF#80  -  []  15 4.5 0 top
NOREF#81  -  []  56.2 0.5 0 top
NOREF#82  -  [unnamed#3]  150.5 36.53 0 top
NOREF#83  -  [unnamed#3]  65.33 27.26 0 top
NOREF#84  -  []  7.5 9.35 0 top
NOREF#85  -  []  36.14 14.57 90 top
NOREF#86  -  []  143.35 2.95 0 top
NOREF#87  -  []  64.38 53.15 0 top
NOREF#88  -  []  173.48 80.2 90 top
NOREF#89  -  []  62.67 64.68 0 top
NOREF#90  -  []  194.54 86.45 90 top
NOREF#91  -  []  45.5 0 0 top
NOREF#92  -  [unnamed#3]  81.92 82.25 0 top
NOREF#93  -  []  206.51 104.38 0 top
NOREF#94  -  [unnamed#3]  150.5 82.25 0 top
NOREF#95  -  []  132.04 3.45 0 top
NOREF#96  -  []  63.68 75.71 0 top
NOREF#97  -  []  15 12.75 0 top
NOREF#98  -  []  168.7 73.16 90 top
NOREF#99  -  []  63.23 61.46 0 top
NOREF#100  -  []  173.44 37.35 90 top
NOREF#101  -  []  183.51 63.34 90 top
NOREF#102  -  []  183.51 72.74 90 top
NOREF#103  -  []  7.5 9.35 0 top
NOREF#104  -  []  173.66 58.92 90 top
NOREF#105  -  [unnamed#3]  9.88 98.64 0 top
NOREF#106  -  []  7.5 104.88 0 top
NOREF#107  -  []  194.6 58.48 90 top
NOREF#108  -  []  144.74 5.32 0 top
NOREF#109  -  [unnamed#3]  81.92 36.53 0 top
NOREF#110  -  []  173.66 44.83 90 top
NOREF#111  -  []  159.67 41.35 0 top
NOREF#112  -  []  68.88 38.66 90 top
NOREF#113  -  []  205.36 96.07 90 top
NOREF#114  -  []  194.6 64.73 0 top
NOREF#115  -  []  56.2 7.45 0 top
NOREF#116  -  []  195.18 59.06 0 top
NOREF#117  -  []  230.62 46.71 90 top
NOREF#118  -  [unnamed#3]  242.37 101.24 180 bottom
NOREF#119  -  [unnamed#3]  244.47 21.49 180 bottom
NOREF#120  -  [unnamed#3]  9.88 98.64 180 bottom
Q1  FDV305N  [SOT23]  17.41 76.28 0 bottom
Q2  FDV305N  [SOT23]  21.09 76.28 0 bottom
Q3  FDV305N  [SOT23]  24.77 76.28 0 bottom
Q4  FDV305N  [SOT23]  29.47 71.83 0 bottom
Q5  FDV305N  [SOT23]  28.46 76.28 0 bottom
Q6  FDV305N  [SOT23]  32.27 76.28 0 bottom
Q7  FDV305N  [SOT23]  246.26 40.72 90 bottom
Q8  FDV305N  [SOT23]  246.26 44.78 90 bottom
Q9  FDV305N  [SOT23]  246.9 40.72 270 top
Q10  FDV305N  [SOT23]  246.26 36.65 90 bottom
Q11  FDV305N  [SOT23]  246.9 36.65 270 top
Q12  FDV305N  [SOT23]  246.9 44.78 270 top
Q13  PSMN1R0-30YLD  [NFET_PSMN1R0-30YLD]  218.96 80.85 180 top
Q14  SI2302CDS-T1-GE3  [SOT23]  213.49 89.49 270 bottom
Q15  FDV305N  [SOT23]  14.79 103.91 0 top
R1  240  [0402]  96.74 24.85 270 bottom
R2  240  [0402]  117.06 24.82 270 bottom
R3  240  [0402]  95.33 25.8 90 bottom
R4  240  [0402]  115.65 25.79 90 bottom
R7  240  [0402]  86.6 25.43 0 bottom
R8  240  [0402]  106.9 25.01 270 bottom
R9  240  [0402]  85.18 25.8 90 bottom
R10  240  [0402]  105.49 25.82 90 bottom
R13  1K  [0402]  70.2 28.98 270 bottom
R14  1K  [0402]  74.59 28.54 180 bottom
R15  1K  [0402]  70.99 27.33 90 bottom
R16  1K  [0402]  72.8 27.33 270 bottom
R17  1K  [0402]  67.74 27.46 270 bottom
R18  1K  [0402]  74.99 27.3 90 bottom
R19  1K  [0402]  70.2 26.51 270 bottom
R20  1K  [0402]  72.8 26.51 270 bottom
R21  1K  [0402]  70.2 25.69 90 bottom
R22  1K  [0402]  72.8 28.15 270 bottom
R23  1K  [0402]  72.8 28.98 270 bottom
R24  240  [0402]  75.89 24.93 270 bottom
R25  240  [0402]  74.99 25.72 90 bottom
R27  36  [0402]  70.67 15.95 0 bottom
R28  1K  [0402]  77.28 17.15 0 bottom
R29  DNI  [0402]  67.49 16.83 270 bottom
R30  1K  [0402]  67.49 17.66 270 bottom
R31  DNI  [0402]  76.98 19.3 90 bottom
R32  DNI  [0402]  66.91 23.43 270 bottom
R33  0  [0402]  76.98 20.17 270 bottom
R34  36  [0402]  66.91 22.61 90 bottom
R35  36  [0402]  72.22 22.85 180 bottom
R36  36  [0402]  73.11 22.85 180 bottom
R37  240  [0402]  117.91 82.89 0 bottom
R39  240  [0402]  130.31 24.77 270 bottom
R40  240  [0402]  140.47 24.77 270 bottom
R41  240  [0402]  128.87 25.71 90 bottom
R42  240  [0402]  139.03 25.71 90 bottom
R45  240  [0402]  150.63 24.77 270 bottom
R46  240  [0402]  160.34 24.85 270 bottom
R47  240  [0402]  149.19 25.71 90 bottom
R48  240  [0402]  159.35 25.71 90 bottom
R51  1K  [0402]  164.71 28.91 270 bottom
R52  1K  [0402]  169.11 28.46 180 bottom
R53  1K  [0402]  165.51 27.26 90 bottom
R54  1K  [0402]  167.31 27.26 270 bottom
R55  1K  [0402]  162.25 27.39 270 bottom
R56  1K  [0402]  169.51 27.23 90 bottom
R57  1K  [0402]  164.71 26.44 270 bottom
R58  1K  [0402]  167.31 26.44 270 bottom
R59  1K  [0402]  164.71 25.62 90 bottom
R60  1K  [0402]  167.31 28.08 270 bottom
R61  1K  [0402]  167.31 28.91 270 bottom
R62  240  [0402]  170.4 24.86 270 bottom
R63  240  [0402]  169.5 25.65 90 bottom
R65  36  [0402]  165.82 16.26 0 bottom
R66  1K  [0402]  172.1 17.46 90 bottom
R67  DNI  [0402]  162.91 17.54 90 bottom
R68  1K  [0402]  162.91 16.74 90 bottom
R69  DNI  [0402]  172.38 19.21 90 bottom
R70  DNI  [0402]  162.01 23.36 270 bottom
R71  0  [0402]  172.38 20.08 270 bottom
R72  36  [0402]  162.01 22.54 90 bottom
R73  36  [0402]  166.68 22.7 180 bottom
R74  36  [0402]  167.57 22.7 180 bottom
R75  240  [0402]  124.33 82.7 0 bottom
R77  0  [1206]  196.15 98.14 180 bottom
R78  0  [1206]  196.15 95.68 180 bottom
R79  0  [0402]  114.19 92.99 0 bottom
R80  10.0K  [0402]  92.82 95.79 270 bottom
R81  10.0K  [0402]  91.14 95.76 90 bottom
R82  10.0K, DNI  [0402]  118.39 92.94 180 bottom
R83  10.0K  [0402]  94.06 104.9 270 bottom
R84  0  [0402]  73.79 98.76 90 bottom
R85  0  [0402]  73.03 100.03 90 bottom
R86  0  [0402]  111.64 92.95 0 bottom
R87  10.0K  [0402]  146.49 98.71 180 bottom
R88  DNI  [0402]  147.34 99.82 180 bottom
R89  DNI  [0402]  145.65 99.82 180 bottom
R90  DNI  [0402]  146.36 92.87 0 bottom
R91  10.0K  [0402]  141.82 94.47 90 bottom
R94  0  [0603]  69.88 93.6 180 bottom
R95  0  [1206]  196.15 103.08 180 bottom
R96  0  [1206]  196.15 105.51 180 bottom
R97  0  [0402]  114.21 100.49 0 bottom
R98  10.0K, DNI  [0402]  100.57 104.88 90 bottom
R99  10.0K  [0402]  102.24 104.88 270 bottom
R100  10.0K  [0402]  70.84 105.44 0 bottom
R101  0  [0402]  72.52 107.39 180 bottom
R102  0  [0402]  111.65 102.59 180 bottom
R103  DNI  [0402]  145.57 107.37 180 bottom
R104  DNI  [0402]  146.57 102.72 180 bottom
R107  0  [0603]  68.18 101.32 0 bottom
R108  240  [0402]  126.45 34.8 270 top
R121  DNI  [0402]  43.19 88.72 90 bottom
R122  0  [0402]  43.19 87.71 90 bottom
R123  10.0K  [0402]  43.95 75.64 270 bottom
R124  10.0K  [0402]  45.85 75.64 270 bottom
R125  1M  [0402]  21.6 70.82 0 bottom
R126  DNI  [0402]  44.08 51.11 90 bottom
R127  0  [0402]  44.08 52.12 90 bottom
R128  10.0K  [0402]  45.93 52.12 270 bottom
R129  10.0K  [0402]  45.93 51.13 270 bottom
R130  1M  [0402]  35.21 67.11 180 bottom
R131  4.7K  [0402]  14.89 84.46 90 bottom
R132  4.7K  [0402]  43.95 76.66 90 bottom
R133  4.7K  [0402]  45.85 76.66 90 bottom
R134  4.7K  [0402]  24.88 79.45 180 bottom
R135  4.7K  [0402]  25.88 79.45 180 bottom
R136  10.0K  [0402]  14.89 82.21 270 bottom
R137  10.0K, DNI  [0402]  14.89 81.21 90 bottom
R138  DNI  [0402]  97.12 66.38 240 bottom
R139  1.50K  [0402]  97.14 56.39 240 bottom
R140  DNI  [0402]  99.59 69.98 0 bottom
R141  499E  [0402]  97.13 67.38 60 bottom
R142  DNI  [0402]  100 66.51 60 bottom
R143  DNI  [0402]  97.12 68.41 240 bottom
R144  DNI  [0402]  97.12 60.88 300 bottom
R145  DNI  [0402]  102.47 69.3 90 bottom
R146  1K  [0402]  104.17 69.95 0 bottom
R147  4.7K  [0402]  50.05 11.01 0 bottom
R148  4.7K  [0402]  50.93 11 180 top
R149  4.7K  [0402]  51.7 11 0 bottom
R150  10.0K  [0402]  53.73 11 0 top
R151  DNI  [0402]  54.24 10.62 90 bottom
R152  DNI  [0402]  54.74 11 180 top
R153  4.7K  [0402]  52.71 11 0 bottom
R154  10.0K  [0402]  55.63 11 0 bottom
R155  10.0K  [0402]  54.24 11.51 270 bottom
R156  4.7K  [0402]  58.17 11 180 bottom
R157  4.7K  [0402]  97.72 33.27 270 bottom
R158  100K  [0402]  73.77 11 0 top
R159  49.9  [0402]  59.21 11 180 top
R160  49.9  [0402]  65.92 11 0 bottom
R161  49.9  [0402]  75 12.35 270 top
R162  49.9  [0402]  78.75 11 0 bottom
R163  49.9  [0402]  80.53 11 0 bottom
R164  49.9  [0402]  125.04 12.35 90 top
R165  49.9  [0402]  96.53 11 0 bottom
R166  49.9  [0402]  60.33 11 180 top
R167  49.9  [0402]  80.53 11 180 top
R168  49.9  [0402]  96.78 11 180 top
R169  49.9  [0402]  120.8 11 180 top
R170  10.0K, DNI  [0402]  48.83 15.57 0 top
R171  10.0K, DNI  [0402]  49.18 19.33 180 top
R172  10.0K, DNI  [0402]  48.43 20.64 90 top
R173  10.0K, DNI  [0402]  58.68 16.33 180 bottom
R174  10.0K  [0402]  57.16 16.72 90 bottom
R175  10.0K  [0402]  48.34 19.33 0 top
R176  10.0K  [0402]  48.67 17.68 0 top
R177  10.0K  [0402]  48.02 15.57 180 top
R178  49.9  [0402]  99 53.85 90 bottom
R179  49.9  [0402]  99.02 51.24 60.6 bottom
R182  150  [0402]  99.85 55.14 120 bottom
R183  10.0K  [0402]  57.92 13.16 90 bottom
R184  0  [0402]  58.04 14.53 270 bottom
R185  0  [0402]  212.43 21.94 270 top
R186  0  [0402]  212.43 22.95 270 top
R187  0,DNI  [0402]  220.73 22.56 270 bottom
R188  0,DNI  [0402]  218.26 50.52 0 bottom
R189  0,DNI  [0402]  218.83 61.04 0 bottom
R190  49.9  [0402]  133.44 55.49 240 bottom
R191  49.9  [0402]  133.44 58.25 240 bottom
R194  150  [0402]  132.67 57.77 240 bottom
R195  10.0K  [0402]  138.36 35.28 0 bottom
R196  0  [0402]  138.36 33.43 0 bottom
R197  DNI  [0402]  132.67 63.29 240 bottom
R198  10.0K  [0402]  2.8 86.57 90 bottom
R199  10.0K  [0402]  2.8 81.36 90 bottom
R200  10.0K  [0402]  2.8 83.52 90 bottom
R201  10.0K  [0402]  2.8 85.55 90 bottom
R202  0  [0402]  2.8 84.53 270 bottom
R203  0  [0402]  2.8 80.34 270 bottom
R204  1K  [0402]  14.87 87.58 90 bottom
R205  0  [0402]  2.8 82.5 270 bottom
R206  1K  [0402]  14.87 88.6 90 bottom
R207  1K  [0402]  14.87 89.61 90 bottom
R208  1K  [0402]  14.87 90.63 90 bottom
R209  240  [0402]  101.48 83.14 90 bottom
R210  2K  [0402]  97.74 82.13 270 bottom
R211  10.0K  [0402]  1.47 14.32 270 top
R212  10.0K  [0402]  5.6 24.43 180 top
R213  1K  [0402]  99.58 82.14 90 bottom
R214  10.0K  [0402]  103.86 82.64 180 bottom
R215  10.0K  [0402]  104.86 82.64 180 bottom
R216  1K  [0402]  101.49 82.18 90 bottom
R217  10.0K  [0402]  105.85 82.64 180 bottom
R218  10.0K  [0402]  107.83 82.76 180 bottom
R219  10.0K  [0402]  106.85 82.64 180 bottom
R220  0  [0402]  128.43 82.67 0 bottom
R221  0  [0402]  127.43 82.67 0 bottom
R223  1K  [0402]  61.22 19.64 90 top
R224  4.7K  [0402]  54.67 29.57 90 bottom
R225  1K  [0402]  59.32 17.1 0 top
R226  10.0K  [0402]  51.32 16.84 0 top
R227  10.0K  [0402]  50.43 16.84 0 top
R228  4.7K  [0402]  54.31 21.01 270 bottom
R229  0  [0402]  61.22 28.03 270 top
R230  0  [0402]  61.22 27.02 270 top
R231  0  [0402]  61.25 26.09 270 top
R232  0  [0402]  61.25 25.07 270 top
R235  0  [0402]  47.76 24.08 90 top
R236  0  [0402]  47.76 25.1 90 top
R237  0  [0402]  49 22.38 180 top
R239  0  [0402]  49.13 27.66 180 bottom
R241  DNI  [0402]  50.43 33.86 0 top
R242  1K  [0402]  49.41 33.86 0 top
R243  DNI  [0402]  46.87 43.26 180 top
R244  1K  [0402]  47.89 43.26 180 top
R245  DNI  [0402]  52.46 33.86 0 top
R246  1K  [0402]  51.44 33.86 0 top
R247  DNI  [0402]  52.59 41.61 90 top
R248  1K  [0402]  52.59 40.59 90 top
R249  0  [0402]  47.38 33.86 180 top
R250  0  [0402]  48.39 33.86 180 top
R251  1K  [0402]  45.85 43.26 180 top
R252  0  [0402]  52.59 36.53 270 top
R253  1K  [0402]  44.84 43.26 180 top
R254  0  [0402]  52.59 37.54 270 top
R255  0  [0402]  52.59 38.56 270 top
R256  0  [0402]  52.59 39.58 270 top
R257  DNI  [0402]  45.35 33.86 0 top
R258  0  [0402]  44.33 33.86 180 top
R259  0  [0402]  49.92 43.26 0 top
R260  1K  [0402]  46.36 33.86 0 top
R261  0  [0402]  43.31 33.86 180 top
R262  0  [0402]  48.9 43.26 0 top
R263  1K  [0402]  42.93 35.64 270 top
R264  DNI  [0402]  42.93 36.65 270 top
R267  1K  [0402]  62.36 43.08 180 top
R268  DNI  [0402]  58.81 45.31 270 top
R269  DNI  [0402]  52.59 44.66 270 top
R270  1K  [0402]  54.49 44.66 90 top
R271  DNI  [0402]  52.59 43.64 270 top
R272  1K  [0402]  52.59 42.62 270 top
R281  10.0K  [0402]  2.8 76.66 270 bottom
R282  10.0K  [0402]  2.8 77.93 270 bottom
R283  10.0K  [0402]  2.8 79.2 270 bottom
R284  1K  [0402]  14.36 79.33 90 bottom
R285  1K  [0402]  14.36 77.93 90 bottom
R286  1K  [0402]  14.36 76.66 90 bottom
R287  1K  [0402]  14.36 75.39 90 bottom
R288  10.0K  [0402]  2.8 75.39 270 bottom
R291  1K  [0402]  216.29 62.44 270 bottom
R292  1K  [0402]  216.29 61.42 270 bottom
R293  DNI  [0402]  218.19 65.74 270 bottom
R294  1K  [0402]  216.29 65.74 270 bottom
R303  DNI  [0402]  216.29 63.71 270 bottom
R304  1K  [0402]  216.29 64.72 270 bottom
R305  4.7K  [0402]  19.48 107.19 0 top
R306  10.0K  [0402]  20.42 109.45 90 top
R307  4.7K  [0402]  18.47 107.19 0 top
R308  10.0K  [0402]  16.62 109.54 270 top
R309  DNI  [0402]  18.51 104.22 180 top
R310  DNI  [0402]  19.78 104.22 180 top
R311  4.7K, DNI  [0402]  19.78 102.44 0 top
R312  4.7K, DNI  [0402]  18.51 102.44 0 top
R313  0  [0402]  17.12 105.74 270 top
R314  0  [0402]  19 105.92 90 top
R315  10.0K  [0402]  14.61 58.63 90 bottom
R316  10.0K  [0402]  14.61 57.61 90 bottom
R317  1K  [0402]  2.67 57.61 180 bottom
R318  1K  [0402]  2.67 59.39 180 bottom
R319  1K  [0402]  2.67 61.17 180 bottom
R320  1K  [0402]  2.67 62.94 180 bottom
R321  10.0K  [0402]  14.61 61.67 90 bottom
R322  4.7K  [0402]  28.96 100.66 180 bottom
R323  4.7K  [0402]  29.98 100.66 180 bottom
R324  0  [0402]  29.85 93.55 0 bottom
R325  0  [0402]  28.84 93.55 0 bottom
R326  0  [0402]  14.61 62.69 90 bottom
R327  4.7K  [0402]  55.38 33.23 90 bottom
R328  4.7K  [0402]  55.38 34.24 90 bottom
R329  10.0K  [0402]  66.05 32.97 270 bottom
R330  10.0K  [0402]  66.05 33.99 270 bottom
R331  4.7K  [0402]  44.3 32.43 270 bottom
R332  DNI  [0402]  20.33 100.79 180 bottom
R333  4.7K  [0402]  46.03 32.4 90 bottom
R335  4.7K  [0402]  43.85 22.84 270 top
R336  4.7K  [0402]  45.64 22.86 90 top
R337  10.0K  [0402]  14.61 60.66 90 bottom
R338  200  [0402]  2.45 70.31 0 bottom
R339  DNI  [0402]  21.34 93.42 180 bottom
R340  DNI  [0402]  22.36 93.42 180 bottom
R341  DNI  [0402]  23.38 93.42 180 bottom
R342  200  [0402]  6.97 65.61 180 bottom
R343  200  [0402]  6.08 65.61 180 bottom
R344  4.7K  [0402]  21.6 97.61 180 bottom
R345  4.7K  [0402]  22.61 97.61 180 bottom
R346  4.7K  [0402]  23.38 100.79 180 bottom
R347  DNI  [0402]  14.49 93.42 180 bottom
R348  DNI  [0402]  15.5 93.42 180 bottom
R349  DNI  [0402]  16.52 93.42 180 bottom
R350  200  [0402]  10.58 72.6 0 bottom
R351  4.7K  [0402]  14.49 100.79 180 bottom
R352  4.7K  [0402]  15.5 100.79 180 bottom
R353  4.7K  [0402]  16.52 100.79 180 bottom
R354  200  [0402]  15.96 65.61 180 bottom
R355  200  [0402]  15.07 65.61 180 bottom
R356  56.2  [0402]  249.82 41.48 90 bottom
R357  2K  [0402]  249.82 45.93 90 bottom
R358  DNI  [0402]  249.82 45.04 270 bottom
R359  56.2  [0402]  249.82 39.83 90 bottom
R360  10.0K  [0402]  243.47 44.27 0 bottom
R361  56.2  [0402]  249.82 38.43 90 bottom
R362  49.9  [0402]  249.82 44.02 90 bottom
R363  56.2  [0402]  249.82 36.53 90 bottom
R364  56.2  [0402]  249.82 42.75 90 bottom
R365  10.0K  [0402]  245.63 65.23 270 bottom
R366  10.0K  [0402]  245.5 57.1 270 bottom
R367  10.0K  [0402]  245.5 63.2 270 bottom
R368  1K  [0402]  245.63 66.25 270 bottom
R369  1K  [0402]  245.5 62.18 270 bottom
R370  1K  [0402]  245.5 58.12 270 bottom
R371  DNI  [0402]  242.01 105.26 180 top
R372  0  [0402]  19.95 22.43 0 top
R373  DNI  [0402]  6.1 27.13 270 top
R374  100K  [0402]  40.9 33.31 270 bottom
R375  0  [0402]  5.72 30.81 180 top
R376  2K  [0402]  18.14 22.43 0 top
R377  2K  [0402]  19.04 22.43 0 top
R378  22  [0402]  17.23 22.43 180 top
R381  10.0K, DNI  [0402]  7.32 33.12 90 top
R382  10.0K  [0402]  7.32 31.35 90 top
